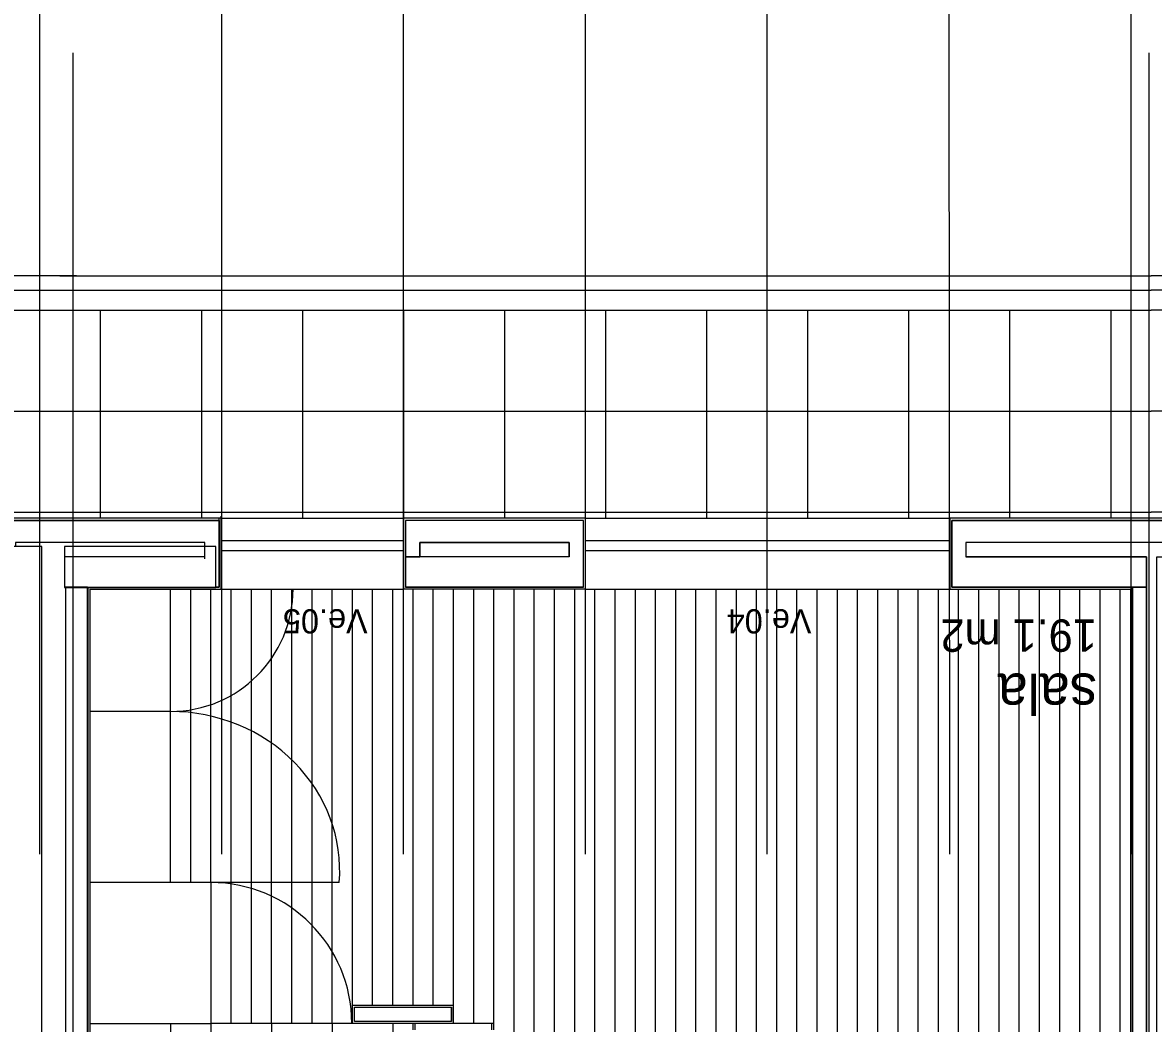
# Model space of a CAD drawing. Extents: x 1248 to 1356, y -443 to -224.
# Drawn here: x 1318.31 to 1323.9, y -234.42 to -229.47 of the extents above; entities that cross this region are included whole.
import ezdxf

# ---------------------------------------------------------------- set-up
doc = ezdxf.new("R2010")
doc.units = 0
for name, color, linetype in [('corte', 7, 'Continuous'), ('estereoctomias', 7, 'Continuous'), ('Level 1', 7, 'Continuous'), ('Level 10', 7, 'Continuous'), ('Level 13', 7, 'Continuous'), ('Level 2', 7, 'Continuous'), ('Level 3', 7, 'Continuous'), ('Level 4', 7, 'Continuous'), ('Level 40', 7, 'Continuous'), ('Level 60', 7, 'Continuous'), ('revestimentos', 7, 'Continuous'), ('vermelhos-cont', 7, 'Continuous'), ('vermelhos-tracej', 7, 'Continuous')]:
    doc.layers.add(name, color=color, linetype=linetype)

msp = doc.modelspace()

# ---------------------------------------------------------------- linework, layer by layer
at = {"layer": 'corte'}
for p, q in [((1319.281, -231.934), (1318.2037, -231.934)), ((1321.084, -231.934), (1320.204, -231.934)), ((1324.684, -231.934), (1322.907, -231.934)), ((1319.211, -232.044), (1318.2736, -232.044)), ((1321.014, -232.044), (1320.274, -232.044)), ((1324.614, -232.044), (1322.977, -232.044)), ((1319.211, -232.114), (1318.521, -232.114)), ((1321.014, -232.114), (1320.274, -232.114)), ((1323.871, -232.114), (1322.977, -232.114)), ((1323.871, -236.7713), (1323.871, -232.114)), ((1318.5203, -232.264), (1318.5203, -236.7713)), ((1321.084, -232.264), (1320.204, -232.264)), ((1322.907, -232.264), (1323.871, -232.264)), ((1323.801, -238.424), (1323.801, -232.264))]:
    msp.add_line(p, q, dxfattribs=at)
for points in [[(1318.2044, -236.5639), (1318.4044, -236.5639), (1318.4044, -232.0639), (1318.2044, -232.0639)], [(1318.2044, -236.5639), (1318.4044, -236.5639), (1318.4044, -232.0639), (1318.2044, -232.0639)], [(1319.2653, -232.0639), (1318.5153, -232.0639), (1318.5153, -232.2657), (1319.2653, -232.2657)]]:
    msp.add_lwpolyline(points, close=True, dxfattribs=at)
at = {"layer": 'estereoctomias'}
for points in [[(1319.281, -232.264), (1319.2653, -232.264), (1319.2653, -232.0639), (1319.211, -232.0639), (1319.211, -232.044), (1318.2736, -232.044), (1318.2736, -232.0639), (1318.2044, -232.0639), (1318.2037, -231.934), (1319.281, -231.934)], [(1321.084, -232.264), (1321.084, -231.934), (1320.204, -231.934), (1320.204, -232.114), (1320.274, -232.114), (1320.274, -232.044), (1321.014, -232.044), (1321.014, -232.114), (1320.204, -232.114), (1320.204, -232.264)], [(1323.9218, -235.8713), (1323.9218, -232.114), (1324.614, -232.114), (1324.614, -232.044), (1322.977, -232.044), (1322.977, -232.114), (1322.977, -232.114), (1323.871, -232.114), (1323.871, -232.264), (1322.907, -232.264), (1322.907, -231.934), (1324.684, -231.934), (1324.684, -232.264), (1324.0318, -232.264), (1324.0318, -235.8713)], [(1318.5203, -232.264), (1318.5203, -235.8713), (1318.6303, -235.8713), (1318.6303, -232.264)], [(1323.871, -232.264), (1323.871, -235.8713), (1323.801, -235.8713), (1323.801, -232.264)], [(1320.431, -234.344), (1320.431, -234.414), (1319.951, -234.414), (1319.951, -234.344)]]:
    msp.add_lwpolyline(points, close=True, dxfattribs=at)
at = {"layer": 'Level 1'}
for p, q in [((1319.281, -232.264), (1319.281, -231.924)), ((1320.204, -231.934), (1320.204, -232.264)), ((1321.084, -232.264), (1321.084, -231.934)), ((1322.907, -231.934), (1322.907, -232.264)), ((1319.211, -232.124), (1319.211, -232.044)), ((1320.274, -232.044), (1320.274, -232.114)), ((1321.014, -232.114), (1321.014, -232.044)), ((1322.977, -232.044), (1322.977, -232.114)), ((1318.521, -232.114), (1318.521, -232.114)), ((1318.5203, -232.264), (1319.281, -232.264)), ((1318.631, -232.264), (1318.631, -236.904)), ((1323.801, -232.264), (1323.801, -238.424)), ((1319.951, -234.414), (1319.951, -234.344)), ((1319.951, -234.344), (1320.431, -234.344)), ((1320.431, -234.414), (1320.431, -234.344)), ((1320.641, -234.424), (1319.941, -234.424)), ((1320.431, -234.414), (1319.951, -234.414)), ((1320.241, -234.456), (1320.241, -234.424)), ((1320.251, -234.456), (1320.251, -234.424)), ((1320.631, -234.456), (1320.631, -234.424)), ((1320.641, -234.456), (1320.641, -234.424))]:
    msp.add_line(p, q, dxfattribs=at)
at = {"layer": 'Level 10'}
for p, q in [((1315.5933, -230.894), (1318.5759, -230.894)), ((1318.4933, -230.894), (1323.8933, -230.894)), ((1318.6933, -230.894), (1318.6933, -231.924)), ((1319.1933, -230.894), (1319.1933, -231.924)), ((1319.6933, -230.894), (1319.6933, -231.924)), ((1320.1933, -230.894), (1320.1933, -231.924)), ((1320.6933, -230.894), (1320.6933, -231.924)), ((1321.1933, -230.894), (1321.1933, -231.924)), ((1321.6933, -230.894), (1321.6933, -231.924)), ((1322.1933, -230.894), (1322.1933, -231.924)), ((1322.6933, -230.894), (1322.6933, -231.924)), ((1323.1933, -230.894), (1323.1933, -231.924)), ((1323.6933, -230.894), (1323.6933, -231.924)), ((1329.2933, -230.894), (1323.8933, -230.894)), ((1315.5933, -231.394), (1318.5759, -231.394)), ((1318.4933, -231.394), (1323.8933, -231.394)), ((1329.2933, -231.394), (1323.8933, -231.394)), ((1315.5933, -231.894), (1318.5759, -231.894)), ((1318.4933, -231.894), (1323.8933, -231.894)), ((1329.2933, -231.894), (1323.8933, -231.894)), ((1319.141, -233.727), (1319.141, -232.274)), ((1319.241, -233.727), (1319.241, -232.274)), ((1319.341, -234.424), (1319.341, -232.274)), ((1319.441, -234.424), (1319.441, -232.274)), ((1319.541, -234.424), (1319.541, -232.274)), ((1319.641, -234.424), (1319.641, -232.274)), ((1319.741, -234.424), (1319.741, -232.274)), ((1319.841, -234.424), (1319.841, -232.274)), ((1319.941, -234.334), (1319.941, -232.274)), ((1320.041, -234.334), (1320.041, -232.274)), ((1320.141, -234.334), (1320.141, -232.274)), ((1320.241, -234.334), (1320.241, -232.274)), ((1320.341, -234.334), (1320.341, -232.274)), ((1320.441, -234.334), (1320.441, -232.274)), ((1320.541, -234.424), (1320.541, -232.274)), ((1320.641, -234.424), (1320.641, -232.274)), ((1320.741, -238.414), (1320.741, -232.274)), ((1320.841, -238.414), (1320.841, -232.274)), ((1320.941, -238.414), (1320.941, -232.274)), ((1321.041, -238.414), (1321.041, -232.274)), ((1321.141, -238.414), (1321.141, -232.274)), ((1321.241, -238.414), (1321.241, -232.274)), ((1321.341, -236.624), (1321.341, -232.274)), ((1321.441, -236.624), (1321.441, -232.274)), ((1321.541, -236.624), (1321.541, -232.274)), ((1321.641, -236.624), (1321.641, -232.274)), ((1321.741, -236.624), (1321.741, -232.274)), ((1321.841, -236.624), (1321.841, -232.274)), ((1321.941, -236.624), (1321.941, -232.274)), ((1322.041, -236.624), (1322.041, -232.274)), ((1322.141, -236.624), (1322.141, -232.274)), ((1322.241, -236.624), (1322.241, -232.274)), ((1322.341, -236.624), (1322.341, -232.274)), ((1322.441, -236.624), (1322.441, -232.274)), ((1322.541, -236.624), (1322.541, -232.274)), ((1322.641, -236.624), (1322.641, -232.274)), ((1322.741, -236.624), (1322.741, -232.274)), ((1322.841, -236.624), (1322.841, -232.274)), ((1322.941, -236.624), (1322.941, -232.274)), ((1323.041, -236.624), (1323.041, -232.274)), ((1323.141, -236.624), (1323.141, -232.274)), ((1323.241, -236.624), (1323.241, -232.274)), ((1323.341, -236.624), (1323.341, -232.274)), ((1323.441, -236.624), (1323.441, -232.274)), ((1323.541, -236.624), (1323.541, -232.274)), ((1323.641, -236.624), (1323.641, -232.274)), ((1323.741, -236.624), (1323.741, -232.274)), ((1319.941, -234.424), (1319.244, -234.424)), ((1319.541, -234.424), (1319.541, -236.824)), ((1319.841, -234.424), (1319.841, -236.824)), ((1320.141, -234.424), (1320.141, -236.824))]:
    msp.add_line(p, q, dxfattribs=at)
at = {"layer": 'Level 13'}
for p, q in [((1319.041, -233.727), (1319.041, -232.274)), ((1319.241, -233.727), (1318.641, -233.727)), ((1319.241, -233.727), (1319.241, -236.824))]:
    msp.add_line(p, q, dxfattribs=at)
at = {"layer": 'Level 2'}
for p, q in [((1318.5759, -230.724), (1315.5933, -230.724)), ((1318.4933, -230.724), (1323.8933, -230.724)), ((1329.2933, -230.724), (1323.8933, -230.724)), ((1315.5933, -230.794), (1318.5759, -230.794)), ((1318.4933, -230.794), (1323.8933, -230.794)), ((1329.2933, -230.794), (1323.8933, -230.794)), ((1319.291, -231.924), (1320.194, -231.924)), ((1321.094, -231.924), (1322.897, -231.924)), ((1319.291, -232.034), (1320.194, -232.034)), ((1321.094, -232.034), (1322.897, -232.034)), ((1319.291, -232.084), (1320.194, -232.084)), ((1321.094, -232.084), (1322.897, -232.084)), ((1319.291, -232.274), (1320.194, -232.274)), ((1321.094, -232.274), (1322.897, -232.274))]:
    msp.add_line(p, q, dxfattribs=at)
at = {"layer": 'Level 3'}
for q in [(1319.041, -235.634), (1319.241, -234.424)]:
    msp.add_line((1319.041, -234.424), q, dxfattribs=at)
at = {"layer": 'Level 4'}
for p, q in [((1319.041, -232.88), (1318.641, -232.88)), ((1319.8761, -233.727), (1319.041, -233.727)), ((1318.641, -234.424), (1319.041, -234.424))]:
    msp.add_line(p, q, dxfattribs=at)
for centre, radius, start, end in [((1319.041, -232.274), 0.606, 270, 0), ((1319.241, -234.424), 0.697, 0, 90)]:
    msp.add_arc(centre, radius, start, end, dxfattribs=at)
msp.add_ellipse((1319.041, -233.6703), major_axis=(-0.8372, 0), ratio=0.943954, start_param=3.069792, end_param=4.712389, dxfattribs=at)
at = {"layer": 'revestimentos'}
for p, q in [((1318.3903, -231.924), (1318.1944, -231.924)), ((1319.291, -231.924), (1318.3903, -231.924)), ((1319.291, -232.274), (1319.291, -231.914)), ((1320.194, -231.924), (1320.194, -232.274)), ((1321.094, -231.924), (1320.194, -231.924)), ((1321.094, -232.274), (1321.094, -231.924)), ((1324.694, -231.924), (1322.897, -231.924)), ((1322.897, -231.924), (1322.897, -232.274)), ((1318.641, -232.274), (1318.641, -236.824)), ((1318.641, -232.274), (1319.291, -232.274)), ((1321.094, -232.274), (1320.194, -232.274)), ((1322.897, -232.274), (1323.791, -232.274)), ((1323.791, -232.274), (1323.791, -238.414)), ((1319.941, -234.334), (1320.441, -234.334)), ((1319.941, -234.424), (1319.941, -234.334)), ((1320.441, -234.424), (1320.441, -234.334))]:
    msp.add_line(p, q, dxfattribs=at)
at = {"layer": 'vermelhos-cont'}
for p, q in [((1318.5594, -250.7923), (1318.5594, -229.6198)), ((1323.884, -250.7923), (1323.884, -229.6198))]:
    msp.add_line(p, q, dxfattribs=at)
at = {"layer": 'vermelhos-tracej'}
for p, q in [((1318.394, -233.587), (1318.394, -228.3936)), ((1319.294, -233.587), (1319.294, -228.3936)), ((1320.194, -233.587), (1320.194, -228.3936)), ((1321.094, -233.587), (1321.094, -228.3936)), ((1321.994, -233.587), (1321.994, -228.3936)), ((1322.897, -233.587), (1322.894, -228.3936)), ((1323.794, -233.587), (1323.794, -228.3936))]:
    msp.add_line(p, q, dxfattribs=at)

# ---------------------------------------------------------------- texts
at = {"layer": 'Level 40'}
for s, p in [('Ve.05', (1320.0163, -232.3738)), ('Ve.04', (1322.2125, -232.3738))]:
    msp.add_text(s, height=0.12, rotation=180, dxfattribs=at).set_placement(p)
at = {"layer": 'Level 60'}
for s, height, p in [('19.1 m2', 0.16, (1323.6246, -232.4246)), ('sala', 0.2, (1323.6246, -232.6924))]:
    msp.add_text(s, height=height, rotation=180, dxfattribs=at).set_placement(p)

doc.saveas('drawing.dxf')
